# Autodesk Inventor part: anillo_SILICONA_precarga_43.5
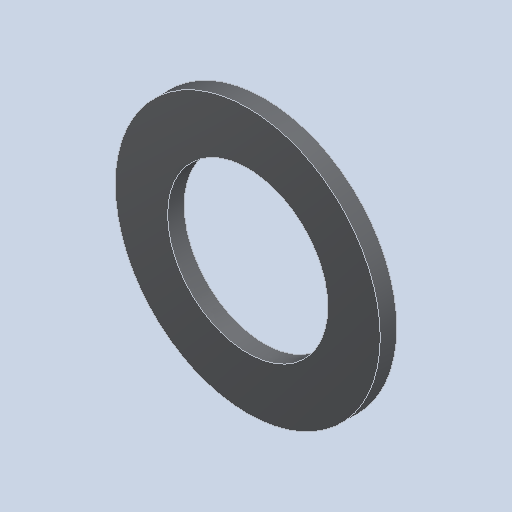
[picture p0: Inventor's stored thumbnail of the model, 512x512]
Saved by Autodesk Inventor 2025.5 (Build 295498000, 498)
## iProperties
Created: 2026-10
Part Number: anillo_SILICONA_precarga_43.5
Material: Genérico
Document SubType Name: Modeling
Designer: Luis M
Density: 1 g/cm^3
Appearance: Valor por defecto
Author: Luis M
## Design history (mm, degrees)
feature "Base1"
node "Sólido1"
